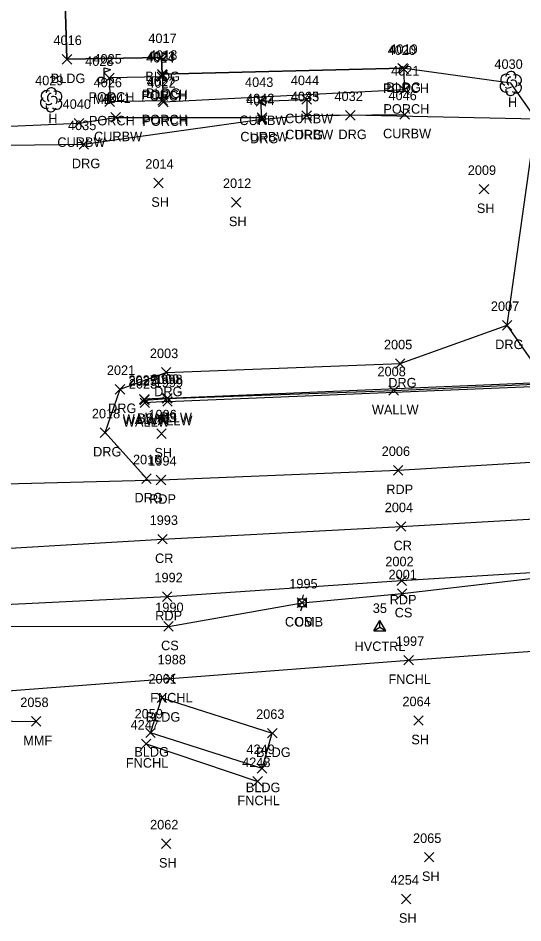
# Model space of a CAD drawing. Extents: x 1509053 to 1511576, y 400838 to 402572.
# Drawn here: x 1510741.8 to 1510847.9, y 401585.9 to 401775.8 of the extents above; entities that cross this region are included whole.
import ezdxf

# ---------------------------------------------------------------- set-up
doc = ezdxf.new("R2010")
doc.units = 0
for name, color, linetype in [('C_A', 7, 'Continuous'), ('C_I', 7, 'Continuous'), ('CPSM', 7, 'Continuous'), ('L_A', 7, 'Continuous'), ('L_I', 7, 'Continuous'), ('L_TIC', 7, 'Continuous'), ('LBC', 7, 'Continuous'), ('LBF', 7, 'Continuous'), ('LDEFAULT', 7, 'Continuous'), ('LELB', 7, 'Continuous'), ('LFNC', 7, 'Continuous'), ('LMB', 7, 'Continuous'), ('LSOGP', 7, 'Continuous'), ('LTD', 7, 'Continuous'), ('LW', 7, 'Continuous'), ('P_A', 7, 'Continuous'), ('P_I', 7, 'Continuous'), ('P_TIC', 7, 'Continuous'), ('PET', 7, 'Continuous'), ('PRC', 7, 'Continuous'), ('R_A', 7, 'Continuous'), ('R_I', 7, 'Continuous'), ('R_TIC', 7, 'Continuous'), ('RC', 7, 'Continuous'), ('RDG', 7, 'Continuous'), ('U_A', 7, 'Continuous'), ('U_I', 7, 'Continuous'), ('UP', 7, 'Continuous')]:
    doc.layers.add(name, color=color, linetype=linetype)

msp = doc.modelspace()

# ---------------------------------------------------------------- linework, layer by layer
at = {"layer": 'CPSM'}
for p, q in [((1510816.57, 401647.22), (1510817.82, 401649.39)), ((1510819.07, 401647.22), (1510817.82, 401649.39)), ((1510817.82, 401647.94), (1510817.82, 401649.39)), ((1510816.57, 401647.22), (1510817.82, 401647.94)), ((1510816.57, 401647.22), (1510819.07, 401647.22)), ((1510817.82, 401647.94), (1510817.82, 401647.94)), ((1510817.82, 401647.94), (1510819.07, 401647.22))]:
    msp.add_line(p, q, dxfattribs=at)
at = {"layer": 'L_TIC'}
for points in [[(1510751.08, 401766.19), (1510753.08, 401768.19)], [(1510753.08, 401766.19), (1510751.08, 401768.19)], [(1510770.96, 401766.6), (1510772.96, 401768.6)], [(1510772.96, 401766.6), (1510770.96, 401768.6)], [(1510821.61, 401764.33), (1510823.61, 401766.33)], [(1510823.61, 401764.33), (1510821.61, 401766.33)], [(1510821.88, 401764.11), (1510823.88, 401766.11)], [(1510823.88, 401764.11), (1510821.88, 401766.11)], [(1510759.99, 401762.28), (1510761.99, 401764.28)], [(1510761.99, 401762.28), (1510759.99, 401764.28)], [(1510771.07, 401762.5), (1510773.07, 401764.5)], [(1510773.07, 401762.5), (1510771.07, 401764.5)], [(1510771.1, 401763.08), (1510773.1, 401765.08)], [(1510773.1, 401763.08), (1510771.1, 401765.08)], [(1510771.21, 401762.82), (1510773.21, 401764.82)], [(1510773.21, 401762.82), (1510771.21, 401764.82)], [(1510821.96, 401759.77), (1510823.96, 401761.77)], [(1510823.96, 401759.77), (1510821.96, 401761.77)], [(1510760.07, 401757.31), (1510762.07, 401759.31)], [(1510762.07, 401757.31), (1510760.07, 401759.31)], [(1510771.18, 401757.55), (1510773.18, 401759.55)], [(1510773.18, 401757.55), (1510771.18, 401759.55)], [(1510771.32, 401757.21), (1510773.32, 401759.21)], [(1510773.32, 401757.21), (1510771.32, 401759.21)], [(1510770.32, 401740.22), (1510772.32, 401742.22)], [(1510772.32, 401740.22), (1510770.32, 401742.22)], [(1510838.73, 401738.92), (1510840.72, 401740.92)], [(1510840.72, 401738.92), (1510838.73, 401740.92)], [(1510786.63, 401736.16), (1510788.63, 401738.16)], [(1510788.63, 401736.16), (1510786.63, 401738.16)], [(1510819.75, 401696.64), (1510821.75, 401698.64)], [(1510821.75, 401696.64), (1510819.75, 401698.64)], [(1510767.35, 401694.84), (1510769.35, 401696.84)], [(1510769.35, 401694.84), (1510767.35, 401696.84)], [(1510767.39, 401694.64), (1510769.39, 401696.64)], [(1510769.39, 401694.64), (1510767.39, 401696.64)], [(1510767.44, 401694.06), (1510769.44, 401696.06)], [(1510769.44, 401694.06), (1510767.44, 401696.06)], [(1510772.11, 401694.98), (1510774.11, 401696.98)], [(1510774.11, 401694.98), (1510772.11, 401696.98)], [(1510772.2, 401695.05), (1510774.2, 401697.05)], [(1510774.2, 401695.05), (1510772.2, 401697.05)], [(1510772.2, 401695.05), (1510774.2, 401697.05)], [(1510774.2, 401695.05), (1510772.2, 401697.05)], [(1510772.22, 401694.35), (1510774.22, 401696.35)], [(1510774.22, 401694.35), (1510772.22, 401696.35)], [(1510770.96, 401687.59), (1510772.96, 401689.59)], [(1510772.96, 401687.59), (1510770.96, 401689.59)], [(1510821.51, 401654.01), (1510823.51, 401656.02)], [(1510823.51, 401654.01), (1510821.51, 401656.02)], [(1510800.49, 401652.09), (1510802.49, 401654.09)], [(1510802.49, 401652.09), (1510800.49, 401654.09)], [(1510772.42, 401647.12), (1510774.42, 401649.12)], [(1510774.42, 401647.12), (1510772.42, 401649.12)], [(1510822.89, 401640.02), (1510824.89, 401642.02)], [(1510824.89, 401640.02), (1510822.89, 401642.02)], [(1510772.82, 401636.15), (1510774.82, 401638.15)], [(1510774.82, 401636.15), (1510772.82, 401638.15)], [(1510771.03, 401632.11), (1510773.02, 401634.11)], [(1510773.02, 401632.11), (1510771.03, 401634.11)], [(1510744.62, 401627.18), (1510746.62, 401629.18)], [(1510746.62, 401627.18), (1510744.62, 401629.18)], [(1510824.95, 401627.36), (1510826.95, 401629.36)], [(1510826.95, 401627.36), (1510824.95, 401629.36)], [(1510768.65, 401624.78), (1510770.65, 401626.78)], [(1510770.65, 401624.78), (1510768.65, 401626.78)], [(1510794.22, 401624.7), (1510796.22, 401626.7)], [(1510796.22, 401624.7), (1510794.22, 401626.7)], [(1510767.72, 401622.46), (1510769.72, 401624.46)], [(1510769.72, 401622.46), (1510767.72, 401624.46)], [(1510792.07, 401617.31), (1510794.07, 401619.31)], [(1510794.07, 401617.31), (1510792.07, 401619.31)], [(1510791.16, 401614.58), (1510793.16, 401616.58)], [(1510793.16, 401614.58), (1510791.16, 401616.58)], [(1510771.94, 401601.49), (1510773.94, 401603.49)], [(1510773.94, 401601.49), (1510771.94, 401603.49)], [(1510827.18, 401598.65), (1510829.18, 401600.65)], [(1510829.18, 401598.65), (1510827.18, 401600.65)], [(1510822.35, 401589.89), (1510824.35, 401591.89)], [(1510824.35, 401589.89), (1510822.35, 401591.89)]]:
    msp.add_lwpolyline(points, dxfattribs=at)
at = {"layer": 'LBC'}
for points in [[(1510751.13, 401798.63), (1510752.08, 401767.19), (1510771.96, 401767.6), (1510772.1, 401764.08), (1510822.61, 401765.33)], [(1510769.65, 401625.78), (1510772.02, 401633.11), (1510795.22, 401625.7)], [(1510793.07, 401618.31), (1510769.65, 401625.78)], [(1510793.07, 401618.31), (1510795.22, 401625.7)]]:
    msp.add_lwpolyline(points, dxfattribs=at)
at = {"layer": 'LBF'}
msp.add_lwpolyline([(1510822.88, 401765.11), (1510822.96, 401760.77), (1510772.32, 401758.21), (1510772.21, 401763.82), (1510772.07, 401763.5), (1510760.99, 401763.28), (1510761.07, 401758.31), (1510772.18, 401758.55)], dxfattribs=at)
at = {"layer": 'LDEFAULT'}
msp.add_lwpolyline([(1510700.37, 401600.36), (1510707.87, 401619.22), (1510725.31, 401628.4), (1510745.62, 401628.18)], dxfattribs=at)
at = {"layer": 'LELB'}
for points in [[(1510773.2, 401696.05), (1510852.94, 401699.4)], [(1510773.2, 401696.05), (1510768.35, 401695.84)], [(1510773.42, 401648.12), (1510801.49, 401653.09), (1510822.51, 401655.02), (1510872.35, 401660.8)], [(1510773.42, 401648.12), (1510706.13, 401648)]]:
    msp.add_lwpolyline(points, dxfattribs=at)
at = {"layer": 'LFNC'}
for points in [[(1510614.51, 401587.89), (1510608.95, 401624.6), (1510623.43, 401626.88), (1510653.12, 401627.01), (1510659.85, 401628.01), (1510675.67, 401629.95), (1510724.73, 401633.47), (1510773.82, 401637.15), (1510823.89, 401641.02), (1510977.71, 401652.22)], [(1510768.72, 401623.46), (1510792.16, 401615.58)]]:
    msp.add_lwpolyline(points, dxfattribs=at)
at = {"layer": 'LMB'}
for p, q in [((1510759.91, 401765.4), (1510761.2, 401765.02)), ((1510759.92, 401762.81), (1510759.92, 401765.4)), ((1510759.92, 401764.5), (1510761.2, 401765.01)), ((1510759.26, 401762.8), (1510759.26, 401762.8))]:
    msp.add_line(p, q, dxfattribs=at)
msp.add_circle((1510759.26, 401762.8), 0.656, dxfattribs=at)
at = {"layer": 'LSOGP'}
msp.add_lwpolyline([(1510952.56, 401688.71), (1510946.38, 401688.3), (1510940.2, 401687.88), (1510934.02, 401687.46), (1510927.84, 401687.05), (1510921.66, 401686.63), (1510915.42, 401686.29), (1510909.19, 401685.96), (1510902.96, 401685.62), (1510896.72, 401685.28), (1510890.49, 401684.95), (1510856.51, 401699.23), (1510852.94, 401699.4), (1510844.58, 401711.34), (1510850.68, 401754.64), (1510845.32, 401762.18), (1510822.61, 401765.33), (1510772.1, 401764.08), (1510771.96, 401767.6), (1510752.08, 401767.19), (1510751.13, 401798.63)], dxfattribs=at)
at = {"layer": 'LTD'}
for p, q in [((1510845.32, 401762.18), (1510845.32, 401762.18)), ((1510845.32, 401762.18), (1510845.32, 401762.18)), ((1510748.74, 401758.74), (1510748.74, 401758.74)), ((1510748.74, 401758.74), (1510748.74, 401758.74))]:
    msp.add_line(p, q, dxfattribs=at)
for centre in [(1510845.37, 401763.61), (1510748.79, 401760.17)]:
    msp.add_arc(centre, 1.05, 335.5272, 180.9563, dxfattribs=at)
for centre, major_axis, ratio, start_param, end_param in [((1510844.53, 401762.85), (1.21, -0.51), 0.895232, 1.570796, 4.712389), ((1510846.36, 401762.76), (-1.14, -0.48), 0.949671, 1.570796, 4.712389), ((1510844.24, 401761.47), (0.58, -1.04), 0.959034, 3.141593, 6.283185), ((1510845.11, 401762.64), (-0.208, -0.792), 0.645439, 3.141593, 6.283185), ((1510845.82, 401762.01), (-0.5, 0.667), 0.989748, 3.141593, 6.283185), ((1510846.32, 401761.35), (-1.09, 0.79), 0.841452, 1.570796, 4.712389), ((1510747.95, 401759.41), (1.21, -0.51), 0.895232, 1.570796, 4.712389), ((1510749.78, 401759.32), (-1.14, -0.48), 0.949671, 1.570796, 4.712389), ((1510845.32, 401760.68), (0.26, 1.06), 0.942809, 1.570796, 4.712389), ((1510844.86, 401761.43), (-0.625, -0.083), 0.423636, 0, 3.141593), ((1510747.66, 401758.03), (0.58, -1.04), 0.959034, 3.141593, 6.283185), ((1510748.53, 401759.2), (-0.208, -0.792), 0.645439, 3.141593, 6.283185), ((1510749.24, 401758.57), (-0.5, 0.667), 0.989748, 3.141593, 6.283185), ((1510749.74, 401757.91), (-1.09, 0.79), 0.841452, 1.570796, 4.712389), ((1510748.74, 401757.24), (0.26, 1.06), 0.942809, 1.570796, 4.712389), ((1510748.28, 401757.99), (-0.625, -0.083), 0.423636, 0, 3.141593)]:
    msp.add_ellipse(centre, major_axis=major_axis, ratio=ratio, start_param=start_param, end_param=end_param, dxfattribs=at)
at = {"layer": 'LW'}
for points in [[(1510773.11, 401695.98), (1510820.75, 401697.64), (1510856.51, 401699.23)], [(1510773.22, 401695.35), (1510856.53, 401698.79)], [(1510768.39, 401695.64), (1510773.11, 401695.98)], [(1510768.44, 401695.05), (1510768.39, 401695.64)], [(1510773.22, 401695.35), (1510768.44, 401695.05)]]:
    msp.add_lwpolyline(points, dxfattribs=at)
at = {"layer": 'P_TIC'}
for points in [[(1510820.69, 401679.89), (1510822.69, 401681.89)], [(1510822.69, 401679.89), (1510820.69, 401681.89)], [(1510770.86, 401677.86), (1510772.86, 401679.86)], [(1510772.86, 401677.86), (1510770.86, 401679.86)], [(1510821.28, 401668.1), (1510823.28, 401670.1)], [(1510823.28, 401668.1), (1510821.28, 401670.1)], [(1510771.15, 401665.42), (1510773.15, 401667.42)], [(1510773.15, 401665.42), (1510771.15, 401667.42)], [(1510821.4, 401656.74), (1510823.4, 401658.74)], [(1510823.4, 401656.74), (1510821.4, 401658.74)], [(1510772.15, 401653.37), (1510774.15, 401655.37)], [(1510774.15, 401653.37), (1510772.15, 401655.37)]]:
    msp.add_lwpolyline(points, dxfattribs=at)
at = {"layer": 'PET'}
for points in [[(1510621.58, 401670.53), (1510656.11, 401672.66), (1510671.73, 401673.2), (1510721.32, 401677.33), (1510730.99, 401677.85), (1510771.86, 401678.86), (1510821.69, 401680.89), (1510871.79, 401683.93), (1510921.66, 401686.63), (1510971.11, 401689.96), (1511022.19, 401694.13), (1511068.96, 401697.4)], [(1510069.7, 401647.38), (1510070.82, 401637.95), (1510072.41, 401628.04), (1510122.3, 401634.81), (1510170.19, 401640.65), (1510220.23, 401643.86), (1510269.72, 401644.29), (1510320.63, 401641.42), (1510370.24, 401637.87), (1510421.73, 401637.03), (1510472.3, 401638.25), (1510523.24, 401640.81), (1510571.7, 401643.53), (1510622.45, 401646.41), (1510672.72, 401649.13), (1510722.86, 401651.91), (1510723.41, 401651.94), (1510773.15, 401654.37), (1510822.4, 401657.74), (1510872.35, 401660.8), (1510922.85, 401663.95), (1510967.23, 401666.49), (1511034, 401670.65), (1511071.49, 401673.22)]]:
    msp.add_lwpolyline(points, dxfattribs=at)
at = {"layer": 'PRC'}
msp.add_lwpolyline([(1510070.82, 401637.95), (1510120.23, 401645.42), (1510169.76, 401652.13), (1510220.07, 401655.52), (1510220.14, 401655.43), (1510270.51, 401655.53), (1510320.84, 401653.34), (1510371.03, 401650.53), (1510421.26, 401649.11), (1510471.33, 401650.1), (1510521.34, 401652.38), (1510571.58, 401655.12), (1510621.67, 401657.75), (1510671.66, 401660.66), (1510722.15, 401663.46), (1510772.15, 401666.42), (1510822.28, 401669.1), (1510872.26, 401671.98), (1510872.29, 401672.01), (1510922.21, 401674.96), (1510971.31, 401678.08), (1511022.51, 401681.61), (1511070.2, 401684.98)], dxfattribs=at)
at = {"layer": 'R_TIC'}
for points in [[(1510791.84, 401757.38), (1510793.84, 401759.38)], [(1510793.84, 401757.38), (1510791.84, 401759.38)], [(1510801.46, 401757.76), (1510803.46, 401759.76)], [(1510803.46, 401757.76), (1510801.46, 401759.76)], [(1510801.46, 401754.4), (1510803.46, 401756.4)], [(1510803.46, 401754.4), (1510801.46, 401756.4)], [(1510810.64, 401754.43), (1510812.64, 401756.43)], [(1510812.64, 401754.43), (1510810.64, 401756.43)], [(1510822.03, 401754.6), (1510824.03, 401756.6)], [(1510824.03, 401754.6), (1510822.03, 401756.6)], [(1510753.6, 401752.79), (1510755.6, 401754.79)], [(1510755.6, 401752.79), (1510753.6, 401754.79)], [(1510761.31, 401753.99), (1510763.31, 401755.99)], [(1510763.31, 401753.99), (1510761.31, 401755.99)], [(1510792.05, 401753.95), (1510794.05, 401755.95)], [(1510794.05, 401753.95), (1510792.05, 401755.95)], [(1510792.09, 401753.56), (1510794.09, 401755.56)], [(1510794.09, 401753.56), (1510792.09, 401755.56)], [(1510801.47, 401754.35), (1510803.47, 401756.35)], [(1510803.47, 401754.35), (1510801.47, 401756.35)], [(1510754.64, 401748.32), (1510756.64, 401750.32)], [(1510756.64, 401748.32), (1510754.64, 401750.32)], [(1510843.58, 401710.34), (1510845.58, 401712.34)], [(1510845.58, 401710.34), (1510843.58, 401712.34)], [(1510821.11, 401702.29), (1510823.11, 401704.29)], [(1510823.11, 401702.29), (1510821.11, 401704.29)], [(1510771.93, 401700.45), (1510773.93, 401702.45)], [(1510773.93, 401700.45), (1510771.93, 401702.45)], [(1510762.24, 401696.91), (1510764.24, 401698.91)], [(1510764.24, 401696.91), (1510762.24, 401698.91)], [(1510759.09, 401687.8), (1510761.09, 401689.8)], [(1510761.09, 401687.8), (1510759.09, 401689.8)], [(1510767.79, 401678.15), (1510769.79, 401680.15)], [(1510769.79, 401678.15), (1510767.79, 401680.15)]]:
    msp.add_lwpolyline(points, dxfattribs=at)
at = {"layer": 'RC'}
msp.add_lwpolyline([(1510702.56, 401743.29), (1510702.39, 401751.12), (1510719.36, 401752.21), (1510754.6, 401753.79), (1510762.31, 401754.99), (1510793.05, 401754.95), (1510792.84, 401758.38), (1510802.46, 401758.76), (1510802.46, 401755.4), (1510823.03, 401755.6)], dxfattribs=at)
at = {"layer": 'RDG'}
for points in [[(1510850.68, 401754.64), (1510811.64, 401755.43), (1510802.47, 401755.35), (1510793.09, 401754.56), (1510755.64, 401749.32), (1510729.66, 401748.97)], [(1510772.93, 401701.45), (1510822.11, 401703.29), (1510844.58, 401711.34)], [(1510763.24, 401697.91), (1510772.93, 401701.45)], [(1510768.79, 401679.15), (1510760.09, 401688.8), (1510763.24, 401697.91)]]:
    msp.add_lwpolyline(points, dxfattribs=at)
at = {"layer": 'UP'}
for p, q in [((1510800.66, 401652.26), (1510800.66, 401653.92)), ((1510800.66, 401653.92), (1510802.33, 401653.92)), ((1510801.74, 401654.76), (1510801.49, 401653.92)), ((1510802.33, 401653.92), (1510802.33, 401652.26)), ((1510802.33, 401652.26), (1510800.66, 401652.26)), ((1510801.24, 401651.42), (1510801.49, 401652.26)), ((1510801.49, 401653.09), (1510801.49, 401653.09))]:
    msp.add_line(p, q, dxfattribs=at)
msp.add_circle((1510801.49, 401653.09), 0.833, dxfattribs=at)

# ---------------------------------------------------------------- texts
at = {"layer": 'C_A'}
msp.add_text('HVCTRL', height=2, dxfattribs=at).set_placement((1510812.51, 401642.94))
at = {"layer": 'C_I'}
msp.add_text('35', height=2, dxfattribs=at).set_placement((1510816.35, 401650.94))
at = {"layer": 'L_A'}
for s, p in [('BLDG', (1510748.67, 401762.19)), ('BLDG', (1510768.55, 401762.6)), ('PORCH', (1510818.5, 401760.11)), ('BLDG', (1510819.2, 401760.33)), ('PORCH', (1510756.61, 401758.28)), ('PORCH', (1510767.69, 401758.5)), ('PORCH', (1510767.83, 401758.82)), ('BLDG', (1510768.69, 401759.08)), ('MB', (1510757.57, 401757.8)), ('H', (1510844.75, 401757.18)), ('PORCH', (1510818.58, 401755.77)), ('H', (1510748.17, 401753.74)), ('PORCH', (1510756.69, 401753.31)), ('PORCH', (1510767.8, 401753.55)), ('PORCH', (1510767.94, 401753.21)), ('SH', (1510769.81, 401736.22)), ('SH', (1510838.21, 401734.91)), ('SH', (1510786.12, 401732.16)), ('WALLW', (1510816.16, 401692.64)), ('WALLW', (1510763.81, 401690.64)), ('WALLW', (1510763.86, 401690.05)), ('BS', (1510766.79, 401690.84)), ('WALLW', (1510768.53, 401690.98)), ('WALLW', (1510768.64, 401690.35)), ('BS', (1510771.64, 401691.05)), ('BS', (1510771.64, 401691.05)), ('SH', (1510770.45, 401683.59)), ('CS', (1510820.95, 401650.01)), ('CS', (1510799.93, 401648.09)), ('CS', (1510771.86, 401643.12)), ('FNCHL', (1510819.64, 401636.02)), ('FNCHL', (1510769.57, 401632.15)), ('BLDG', (1510768.62, 401628.11)), ('SH', (1510824.44, 401623.36)), ('MMF', (1510742.9, 401623.18)), ('BLDG', (1510766.24, 401620.78)), ('BLDG', (1510791.81, 401620.7)), ('FNCHL', (1510764.47, 401618.46)), ('BLDG', (1510789.66, 401613.31)), ('FNCHL', (1510787.91, 401610.58)), ('SH', (1510771.42, 401597.49)), ('SH', (1510826.67, 401594.65)), ('SH', (1510821.84, 401585.89))]:
    msp.add_text(s, height=2, dxfattribs=at).set_placement(p)
at = {"layer": 'L_I'}
for s, p in [('4016', (1510749.25, 401770.19)), ('4017', (1510769.19, 401770.6)), ('4020', (1510819.46, 401768.11)), ('4019', (1510819.83, 401768.33)), ('4028', (1510755.92, 401765.8)), ('4025', (1510757.65, 401766.28)), ('4024', (1510768.73, 401766.5)), ('4023', (1510768.87, 401766.82)), ('4018', (1510769.33, 401767.08)), ('4030', (1510841.9, 401765.18)), ('4021', (1510820.19, 401763.77)), ('4029', (1510745.39, 401761.74)), ('4026', (1510757.68, 401761.31)), ('4027', (1510768.84, 401761.55)), ('4022', (1510768.98, 401761.21)), ('2014', (1510768.55, 401744.22)), ('2009', (1510836.3, 401742.91)), ('2012', (1510784.86, 401740.16)), ('2008', (1510817.33, 401700.64)), ('2027', (1510765.01, 401698.84)), ('2025', (1510765.05, 401698.64)), ('2023', (1510765.1, 401698.05)), ('2000', (1510769.7, 401699.05)), ('2000', (1510769.7, 401699.05)), ('1998', (1510770.42, 401698.98)), ('1999', (1510770.52, 401698.35)), ('1996', (1510769.21, 401691.59)), ('2001', (1510819.66, 401658.01)), ('1995', (1510798.8, 401656.09)), ('1990', (1510770.64, 401651.12)), ('1997', (1510821.19, 401644.02)), ('1988', (1510771.13, 401640.15)), ('2061', (1510769.21, 401636.11)), ('2058', (1510742.28, 401631.18)), ('2064', (1510822.57, 401631.36)), ('2059', (1510766.3, 401628.78)), ('2063', (1510791.83, 401628.7)), ('4247', (1510765.46, 401626.46)), ('4249', (1510789.8, 401621.31)), ('4248', (1510788.9, 401618.58)), ('2062', (1510769.55, 401605.49)), ('2065', (1510824.8, 401602.65)), ('4254', (1510820.09, 401593.89))]:
    msp.add_text(s, height=2, dxfattribs=at).set_placement(p)
at = {"layer": 'P_A'}
for s, p in [('RDP', (1510819.18, 401675.89)), ('RDP', (1510769.35, 401673.86)), ('CR', (1510820.71, 401664.1)), ('CR', (1510770.59, 401661.42)), ('RDP', (1510819.89, 401652.74)), ('RDP', (1510770.64, 401649.37))]:
    msp.add_text(s, height=2, dxfattribs=at).set_placement(p)
at = {"layer": 'P_I'}
for s, p in [('2006', (1510818.22, 401683.89)), ('1994', (1510769.17, 401681.86)), ('2004', (1510818.86, 401672.1)), ('1993', (1510769.46, 401669.42)), ('2002', (1510818.98, 401660.74)), ('1992', (1510770.46, 401657.37))]:
    msp.add_text(s, height=2, dxfattribs=at).set_placement(p)
at = {"layer": 'R_A'}
for s, p in [('CURBW', (1510788.31, 401753.38)), ('CURBW', (1510797.93, 401753.76)), ('CURBW', (1510818.5, 401750.6)), ('CURBW', (1510750.07, 401748.79)), ('CURBW', (1510757.78, 401749.99)), ('CURBW', (1510788.52, 401749.95)), ('DRG', (1510790.58, 401749.56)), ('CURBW', (1510797.93, 401750.4)), ('DRG', (1510799.96, 401750.35)), ('DRG', (1510809.13, 401750.43)), ('DRG', (1510753.13, 401744.32)), ('DRG', (1510842.07, 401706.34)), ('DRG', (1510819.6, 401698.29)), ('DRG', (1510770.41, 401696.44)), ('DRG', (1510760.73, 401692.91)), ('DRG', (1510757.58, 401683.8)), ('DRG', (1510766.28, 401674.15))]:
    msp.add_text(s, height=2, dxfattribs=at).set_placement(p)
at = {"layer": 'R_I'}
for s, p in [('4043', (1510789.5, 401761.38)), ('4044', (1510799.12, 401761.76)), ('4045', (1510799.12, 401758.4)), ('4033', (1510799.13, 401758.35)), ('4032', (1510808.3, 401758.43)), ('4046', (1510819.64, 401758.6)), ('4040', (1510751.18, 401756.79)), ('4041', (1510759.54, 401757.99)), ('4042', (1510789.71, 401757.95)), ('4034', (1510789.75, 401757.56)), ('4035', (1510752.3, 401752.32)), ('2007', (1510841.16, 401714.34)), ('2005', (1510818.69, 401706.29)), ('2003', (1510769.51, 401704.45)), ('2021', (1510760.47, 401700.91)), ('2018', (1510757.32, 401691.8)), ('2016', (1510765.96, 401682.15))]:
    msp.add_text(s, height=2, dxfattribs=at).set_placement(p)
at = {"layer": 'U_A'}
msp.add_text('COMB', height=2, dxfattribs=at).set_placement((1510797.88, 401648.09))
at = {"layer": 'U_I'}
msp.add_text('1995', height=2, dxfattribs=at).set_placement((1510798.8, 401656.09))

doc.saveas('drawing.dxf')
